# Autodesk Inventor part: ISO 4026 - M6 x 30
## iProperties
Comments: To add or edit properties for Autodesk Inventor files, use iProperties.
Created: 2004-08
Part Number: ISO 4026 - M6 x 30
Vendor: Autodesk Inc.
Document SubType Name: Modeling
Designer: John Blackburn
Material: Default
Description: Hexagon Socket Set Screw
Standard: ISO 4026
Size Designation: M6 x 30
Alert: To add or edit properties for Autodesk Inventor files, use iProperties.
Control State: 0
Master: False
Checked Out: False
Shininess: 64.0
Length Units: 11269
Angle Units: 11279
Time Units: 11290
Mass Units: 11283
Length Display Precision: 3
Angle Display Precision: 2
Compacted: True
EGR: 1
Density: 0.0
Volumn: 0.0
Area: 0.0
PropertySet Name: Model Information
Author: John Blackburn
Revision Number: 8
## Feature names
1. Body [Revolution]
2. Chamfer1
3. Slot [Extrusion]
4. Chamfer2
